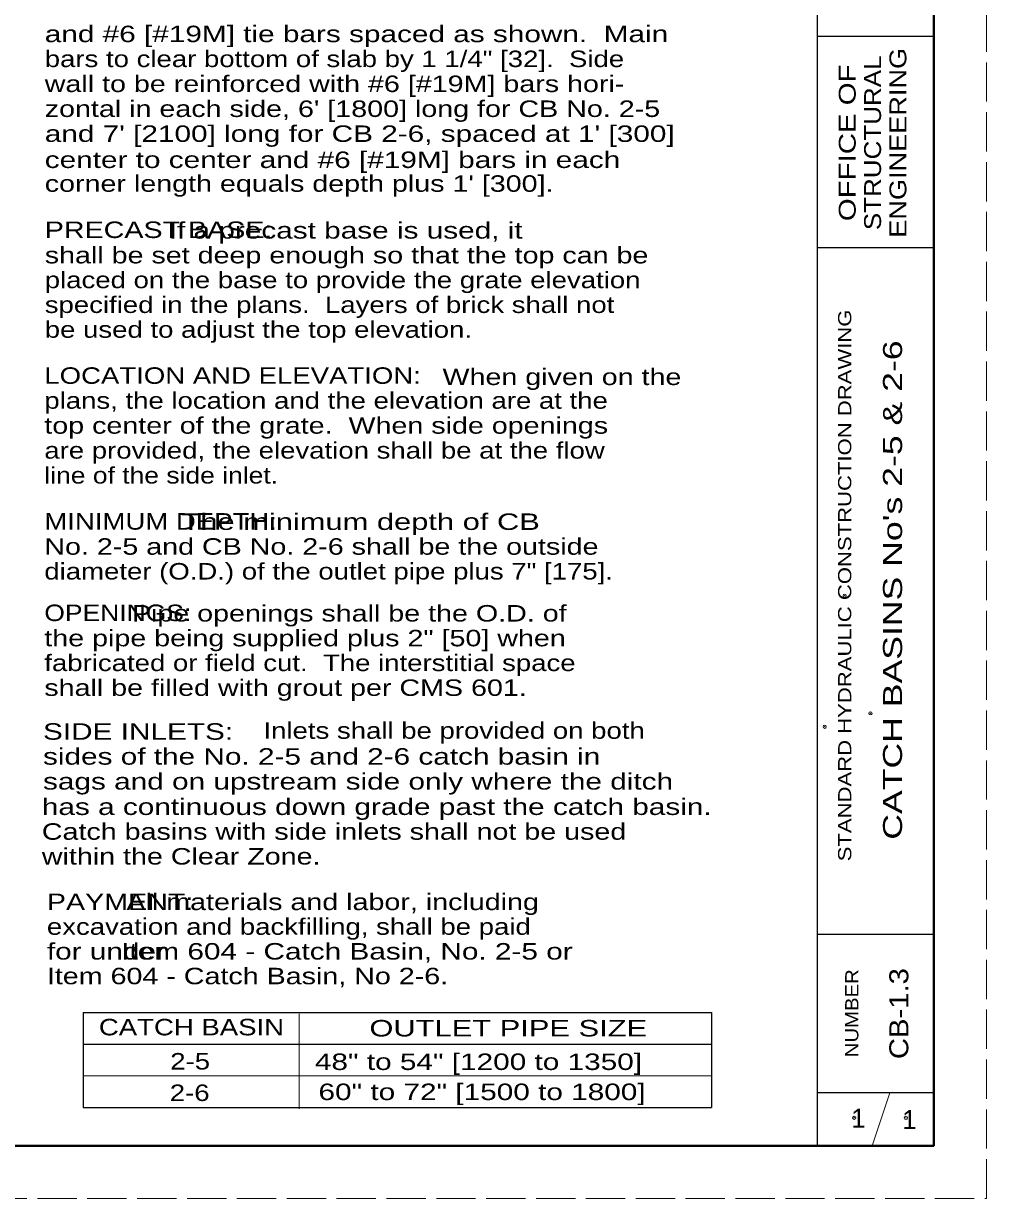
# Model space of a CAD drawing. Extents: x 1329.9 to 1363.9, y 715.5 to 737.5.
# Drawn here: x 1354.75 to 1363.86, y 715.5 to 726.62 of the extents above; entities that cross this region are included whole.
import ezdxf
from ezdxf.enums import TextEntityAlignment as Align

# ---------------------------------------------------------------- set-up
doc = ezdxf.new("R2010")
doc.units = 0
doc.header["$LTSCALE"] = 0.062
doc.header["$PDMODE"] = 32
doc.header["$PDSIZE"] = 0.031
doc.linetypes.add('LONG_DASHED', pattern=[7.5, 6, -1.5])
doc.layers.add('1', color=7, linetype='Continuous', lineweight=13)

msp = doc.modelspace()

# ---------------------------------------------------------------- linework, layer by layer
at = {"layer": '1', "lineweight": 25}
for p, q in [((1362.26333, 715.9975), (1362.26333, 736.9975)), ((1363.36333, 736.9975), (1363.36333, 715.9975)), ((1363.36333, 726.4975), (1362.26333, 726.4975)), ((1363.36333, 724.4975), (1362.26333, 724.4975)), ((1363.36333, 717.9975), (1362.26333, 717.9975)), ((1355.31033, 717.258), (1361.26008, 717.258)), ((1355.31033, 717.258), (1355.31033, 716.35808)), ((1361.26008, 717.258), (1361.26008, 716.35808)), ((1355.31033, 716.958), (1361.26008, 716.958)), ((1363.36333, 716.4975), (1362.26333, 716.4975)), ((1355.31033, 716.35808), (1361.26008, 716.35808))]:
    msp.add_line(p, q, dxfattribs=at)
at = {"layer": '1'}
for p, q in [((1357.3555, 717.24492), (1357.3555, 716.34508)), ((1355.31033, 716.65808), (1361.26008, 716.65808)), ((1362.78, 715.9975), (1362.94667, 716.4975))]:
    msp.add_line(p, q, dxfattribs=at)
at = {"layer": '1', "linetype": 'LONG_DASHED'}
msp.add_lwpolyline([(1329.86333, 715.4975), (1363.86333, 715.4975), (1363.86333, 737.4975), (1329.86333, 737.4975)], close=True, dxfattribs=at)
at = {"layer": '1', "lineweight": 25}
msp.add_lwpolyline([(1363.36333, 715.9975), (1331.86333, 715.9975), (1331.86333, 736.9975)], dxfattribs=at)
at = {"layer": '1', "lineweight": 40}
msp.add_lwpolyline([(1331.86333, 736.9975), (1363.36333, 736.9975), (1363.36333, 715.9975), (1331.86333, 715.9975)], close=True, dxfattribs=at)
msp.add_lwpolyline([(1331.86333, 736.9975), (1363.36333, 736.9975), (1363.36333, 715.9975), (1331.86333, 715.9975)], close=True, dxfattribs=at)
at = {"layer": '1'}
for p in [(1362.52075, 721.2035), (1362.95358, 721.21083), (1362.76442, 720.09067), (1362.33158, 719.96308), (1362.61142, 716.26125), (1363.09983, 716.26025)]:
    msp.add_point(p, dxfattribs=at)

# ---------------------------------------------------------------- texts
for s, width, p in [('and #6 [#19M] tie bars spaced as shown.  Main', 1.35, (1354.94833, 726.44483)), ('bars to clear bottom of slab by 1 1/4" [32].  Side ', 1.25, (1354.94833, 726.20875)), ('wall to be reinforced with #6 [#19M] bars hori-', 1.3, (1354.94833, 725.97267)), ("zontal in each side, 6' [1800] long for CB No. 2-5", 1.3, (1354.94833, 725.73658)), ("and 7' [2100] long for CB 2-6, spaced at 1' [300]", 1.35, (1354.94833, 725.50042)), ('center to center and #6 [#19M] bars in each', 1.35, (1354.94833, 725.25342)), ("corner length equals depth plus 1' [300].", 1.3, (1354.94833, 725.02825)), ('PRECAST BASE:', 1.3, (1354.94833, 724.59067)), ('               If a precast base is used, it', 1.35, (1354.94833, 724.58492)), ('shall be set deep enough so that the top can be', 1.3, (1354.94833, 724.35025)), ('placed on the base to provide the grate elevation', 1.25, (1354.94833, 724.11558)), ('specified in the plans.  Layers of brick shall not', 1.25, (1354.94833, 723.88092)), ('be used to adjust the top elevation.', 1.25, (1354.94833, 723.64625)), ('LOCATION AND ELEVATION:', 1.25, (1354.94425, 723.21033)), ('When given on the', 1.3, (1358.71358, 723.1985)), ('plans, the location and the elevation are at the', 1.25, (1354.94425, 722.97417)), ('top center of the grate.  When side openings', 1.3, (1354.94425, 722.73808)), ('are provided, the elevation shall be at the flow', 1.25, (1354.94425, 722.502)), ('line of the side inlet.', 1.2, (1354.94425, 722.26592)), ('MINIMUM DEPTH:', 1.25, (1354.94425, 721.82975)), ('                The minimum depth of CB', 1.4, (1354.94425, 721.82692)), ('No. 2-5 and CB No. 2-6 shall be the outside', 1.3, (1354.94425, 721.59225)), ('diameter (O.D.) of the outlet pipe plus 7" [175].', 1.25, (1354.94425, 721.35758)), ('OPENINGS:', 1.2, (1354.94425, 720.96408)), ('           Pipe openings shall be the O.D. of', 1.3, (1354.94425, 720.95975)), ('the pipe being supplied plus 2" [50] when', 1.3, (1354.94425, 720.72508)), ('fabricated or field cut.  The interstitial space', 1.25, (1354.94425, 720.49042)), ('shall be filled with grout per CMS 601.', 1.3, (1354.94425, 720.25575)), ('SIDE INLETS:', 1.35, (1354.93175, 719.84075)), ('Inlets shall be provided on both', 1.25, (1357.01867, 719.84942)), ('sides of the No. 2-5 and 2-6 catch basin in ', 1.35, (1354.93175, 719.60475)), ('sags and on upstream side only where the ditch', 1.35, (1354.93175, 719.36875)), ('has a continuous down grade past the catch basin.  ', 1.35, (1354.92075, 719.12842)), ('Catch basins with side inlets shall not be used ', 1.3, (1354.92075, 718.89375)), ('within the Clear Zone. ', 1.3, (1354.92075, 718.65908)), ('          All materials and labor, including', 1.3, (1354.96842, 718.22775)), ('PAYMENT: ', 1.3, (1354.96842, 718.22775)), ('excavation and backfilling, shall be paid', 1.25, (1354.96842, 717.99375)), ('for under ', 1.35, (1354.96842, 717.75975)), ('         Item 604 - Catch Basin, No. 2-5 or', 1.35, (1354.96842, 717.75975)), ('Item 604 - Catch Basin, No 2-6.', 1.3, (1354.96842, 717.52575)), ('CATCH BASIN', 1.25, (1355.46058, 717.042)), ('OUTLET PIPE SIZE', 1.4, (1358.02158, 717.03158)), ('2-5', 1.25, (1356.13617, 716.71858)), ('48" to 54" [1200 to 1350]', 1.35, (1357.5055, 716.71408)), ('2-6', 1.25, (1356.13175, 716.42042)), ('60" to 72" [1500 to 1800]', 1.35, (1357.53942, 716.42925))]:
    msp.add_text(s, height=0.156, dxfattribs=dict(at, width=width)).set_placement(p)
for s, height, width, p in [('STRUCTURAL', 0.16, 1.15, (1362.86508, 725.49196)), ('ENGINEERING', 0.16, 1.2, (1363.10508, 725.49204)), ('OFFICE OF', 0.16, 1.3, (1362.62508, 725.49196)), ('STANDARD HYDRAULIC CONSTRUCTION DRAWING', 0.125, 1.25, (1362.58325, 721.30154)), ("CATCH BASINS No's 2-5 & 2-6", 0.18, 1.4, (1363.06383, 721.25771)), ('NUMBER', 0.125, 1.15, (1362.65033, 717.25158)), ('CB-1.3', 0.18, 1.15, (1363.12325, 717.24788))]:
    msp.add_text(s, height=height, rotation=90, dxfattribs=dict(at, width=width)).set_placement(p, align=Align.CENTER)
for p in [(1362.65118, 716.16758), (1363.13402, 716.155)]:
    msp.add_text('1', height=0.18, dxfattribs=at).set_placement(p, align=Align.CENTER)

doc.saveas('drawing.dxf')
